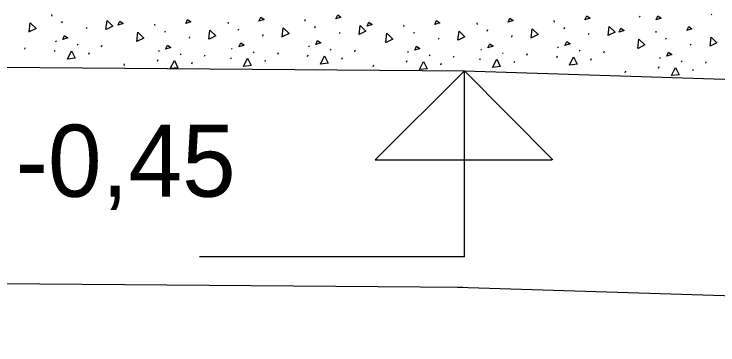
# Model space of a CAD drawing. Extents: x 43.6 to 54.1, y -16.5 to -1.7.
# Drawn here: x 48.509 to 49.485, y -8.702 to -8.243 of the extents above; entities that cross this region are included whole.
import ezdxf

# ---------------------------------------------------------------- set-up
doc = ezdxf.new("R2010")
doc.units = 0
for name, color, linetype in [('KONSTRUKCE_L', 7, 'Continuous'), ('Nová vrstva (1)', 7, 'Continuous'), ('Vrstva 50', 7, 'Continuous')]:
    doc.layers.add(name, color=color, linetype=linetype)

msp = doc.modelspace()

# ---------------------------------------------------------------- linework, layer by layer
at = {"layer": 'KONSTRUKCE_L'}
for p, q in [((46.54927, -8.30077), (49.13382, -8.32145)), ((49.13382, -8.32145), (51.63382, -8.40145))]:
    msp.add_line(p, q, dxfattribs=at)
at = {"layer": 'Nová vrstva (1)'}
for p, q in [((46.54927, -8.60078), (49.13142, -8.62144)), ((49.12422, -8.6213), (51.63382, -8.7016))]:
    msp.add_line(p, q, dxfattribs=at)
at = {"layer": 'Vrstva 50'}
for p, q in [((48.56142, -8.24343), (48.56178, -8.24542)), ((49.37598, -8.24574), (49.37692, -8.24711)), ((49.47593, -8.24264), (49.47687, -8.24391)), ((48.57567, -8.25471), (48.57651, -8.25268)), ((48.80571, -8.25364), (48.80607, -8.25563)), ((48.91232, -8.25034), (48.91268, -8.25233)), ((49.15108, -8.25502), (49.15144, -8.25701)), ((49.25769, -8.25172), (49.25805, -8.25371)), ((48.60972, -8.26279), (48.61046, -8.26077)), ((48.70412, -8.25669), (48.70448, -8.25868)), ((48.71836, -8.26796), (48.7192, -8.26594)), ((48.81996, -8.26492), (48.8208, -8.26289)), ((48.92656, -8.26162), (48.9274, -8.25959)), ((49.04949, -8.25807), (49.04985, -8.26006)), ((49.16533, -8.2663), (49.16617, -8.26427)), ((49.27194, -8.263), (49.27278, -8.26097)), ((48.75242, -8.27615), (48.75316, -8.27412)), ((48.85402, -8.2731), (48.85476, -8.27108)), ((48.96062, -8.2697), (48.96136, -8.26768)), ((49.06373, -8.26935), (49.06457, -8.26732)), ((49.0978, -8.27753), (49.09854, -8.2755)), ((49.19939, -8.27448), (49.20013, -8.27246)), ((49.30599, -8.27108), (49.30673, -8.26906)), ((49.39901, -8.26636), (49.39937, -8.26835)), ((49.41325, -8.27763), (49.41409, -8.27561)), ((48.56672, -8.27989), (48.56766, -8.28126)), ((48.59677, -8.28459), (48.59771, -8.28596)), ((49.44731, -8.28582), (49.44805, -8.28379)), ((48.52408, -8.29127), (48.52492, -8.28925)), ((48.56546, -8.29453), (48.5664, -8.29251)), ((48.63069, -8.28798), (48.63153, -8.28595)), ((48.70942, -8.29324), (48.71035, -8.29442)), ((48.81101, -8.2902), (48.81195, -8.29137)), ((48.84106, -8.2949), (48.842, -8.29617)), ((48.91761, -8.2868), (48.91856, -8.28817)), ((48.94767, -8.2915), (48.94861, -8.29287)), ((48.98159, -8.29488), (48.98243, -8.29286)), ((49.05479, -8.29463), (49.05572, -8.2958)), ((49.15638, -8.29158), (49.15732, -8.29275)), ((49.26299, -8.28818), (49.26393, -8.28955)), ((49.29304, -8.29288), (49.29398, -8.29425)), ((49.32696, -8.29626), (49.3278, -8.29424)), ((48.61298, -8.29811), (48.61382, -8.29609)), ((48.73947, -8.29794), (48.74041, -8.29922)), ((48.77339, -8.30123), (48.77422, -8.2992)), ((48.80975, -8.30484), (48.81069, -8.30281)), ((48.87498, -8.29818), (48.87582, -8.29616)), ((48.91635, -8.30144), (48.91729, -8.29941)), ((48.96388, -8.30502), (48.96472, -8.30299)), ((49.08484, -8.29933), (49.08578, -8.3006)), ((49.11876, -8.30261), (49.1196, -8.30058)), ((49.15512, -8.30622), (49.15606, -8.30419)), ((49.18644, -8.29628), (49.18737, -8.29755)), ((49.22035, -8.29956), (49.22119, -8.29754)), ((49.26173, -8.30282), (49.26266, -8.30079)), ((49.30925, -8.3064), (49.31009, -8.30437)), ((49.4043, -8.30291), (49.40524, -8.30409)), ((48.66179, -8.31382), (48.66263, -8.3118)), ((48.70816, -8.30789), (48.7091, -8.30586)), ((48.75568, -8.31146), (48.75652, -8.30944)), ((48.85728, -8.30842), (48.85812, -8.30639)), ((49.00716, -8.3152), (49.008, -8.31318)), ((49.05353, -8.30927), (49.05447, -8.30724)), ((49.10106, -8.31285), (49.1019, -8.31082)), ((49.20265, -8.3098), (49.20349, -8.30777)), ((49.43436, -8.30762), (49.4353, -8.30889)), ((49.46827, -8.3109), (49.46911, -8.30887)), ((49.13382, -8.32145), (49.01022, -8.44505)), ((49.13382, -8.32145), (49.25622, -8.44505)), ((49.13382, -8.57945), (49.13382, -8.32265)), ((49.35667, -8.32349), (49.35751, -8.32147)), ((49.40304, -8.31756), (49.40398, -8.31553)), ((49.45057, -8.32114), (49.45141, -8.31911)), ((49.01022, -8.44505), (49.25502, -8.44505)), ((49.13382, -8.57945), (48.76662, -8.57945))]:
    msp.add_line(p, q, dxfattribs=at)
for points in [[(48.95551, -8.24924), (48.95804, -8.24367), (48.96254, -8.24683), (48.95551, -8.24924)], [(49.30088, -8.25063), (49.30341, -8.24505), (49.30791, -8.24821), (49.30088, -8.25063)], [(49.39944, -8.25084), (49.40187, -8.24516), (49.40647, -8.24842), (49.39944, -8.25084)], [(48.53017, -8.26758), (48.53159, -8.25483), (48.53973, -8.26279), (48.53037, -8.26747)], [(48.63678, -8.26418), (48.6382, -8.25153), (48.64634, -8.25949), (48.63698, -8.26418)], [(48.65341, -8.25805), (48.65594, -8.25237), (48.66044, -8.25564), (48.65341, -8.25805)], [(48.74731, -8.25569), (48.74984, -8.25001), (48.75434, -8.25328), (48.74731, -8.25569)], [(48.8489, -8.25264), (48.85143, -8.24696), (48.85593, -8.25023), (48.8489, -8.25264)], [(48.99878, -8.25943), (49.00131, -8.25375), (49.00581, -8.25702), (48.99878, -8.25943)], [(49.09268, -8.25707), (49.09521, -8.25139), (49.09971, -8.25466), (49.09268, -8.25707)], [(49.19427, -8.25402), (49.1968, -8.24835), (49.2013, -8.25161), (49.19427, -8.25402)], [(48.77948, -8.27754), (48.7809, -8.26479), (48.78904, -8.27275), (48.77967, -8.27743)], [(48.88107, -8.27449), (48.88249, -8.26174), (48.89063, -8.2697), (48.88127, -8.27438)], [(48.98768, -8.27109), (48.9891, -8.25844), (48.99724, -8.2664), (48.98788, -8.27108)], [(49.12485, -8.27892), (49.12627, -8.26617), (49.13441, -8.27413), (49.12505, -8.27881)], [(49.22644, -8.27587), (49.22786, -8.26312), (49.236, -8.27108), (49.22664, -8.27576)], [(49.33305, -8.27247), (49.33447, -8.25982), (49.34261, -8.26778), (49.33325, -8.27247)], [(49.3483, -8.26772), (49.35083, -8.26204), (49.35533, -8.26531), (49.3483, -8.26772)], [(49.4422, -8.26536), (49.44473, -8.25968), (49.44923, -8.26295), (49.4422, -8.26536)], [(48.57676, -8.27799), (48.5793, -8.27241), (48.5839, -8.27557), (48.57676, -8.27799)], [(48.67953, -8.28063), (48.68094, -8.26789), (48.68909, -8.27585), (48.67972, -8.28053)], [(49.0249, -8.28202), (49.02632, -8.26927), (49.03446, -8.27723), (49.02509, -8.28191)], [(49.47437, -8.28721), (49.47578, -8.27446), (49.48393, -8.28242), (49.47456, -8.2871)], [(48.71946, -8.29134), (48.722, -8.28566), (48.7266, -8.28893), (48.71946, -8.29134)], [(48.82106, -8.28829), (48.82359, -8.28262), (48.82819, -8.28588), (48.82106, -8.28829)], [(48.92766, -8.2849), (48.9302, -8.27932), (48.93479, -8.28248), (48.92766, -8.2849)], [(49.16643, -8.28968), (49.16896, -8.284), (49.17356, -8.28726), (49.16643, -8.28968)], [(49.27303, -8.28628), (49.27557, -8.2807), (49.28016, -8.28386), (49.27303, -8.28628)], [(49.37441, -8.2903), (49.37583, -8.27756), (49.38397, -8.28552), (49.37461, -8.2902)], [(48.58318, -8.30511), (48.58884, -8.29363), (48.59385, -8.30389), (48.58348, -8.3051)], [(49.06484, -8.29272), (49.06737, -8.28704), (49.07197, -8.29031), (49.06484, -8.29272)], [(49.41435, -8.30101), (49.41688, -8.29533), (49.42148, -8.2986), (49.41435, -8.30101)], [(48.82747, -8.31531), (48.83313, -8.30394), (48.83814, -8.31419), (48.82777, -8.3153)], [(48.93408, -8.31202), (48.93974, -8.30054), (48.94475, -8.3108), (48.93438, -8.31201)], [(49.27945, -8.3134), (49.28511, -8.30192), (49.29012, -8.31218), (49.27975, -8.31339)], [(48.72588, -8.31836), (48.73154, -8.30699), (48.73655, -8.31724), (48.72618, -8.31835)], [(49.07125, -8.31974), (49.07691, -8.30837), (49.08192, -8.31862), (49.07155, -8.31973)], [(49.17284, -8.3167), (49.1785, -8.30532), (49.18351, -8.31557), (49.17314, -8.31669)], [(49.42077, -8.32803), (49.42643, -8.31666), (49.43144, -8.32691), (49.42107, -8.32802)]]:
    msp.add_lwpolyline(points, dxfattribs=at)

# ---------------------------------------------------------------- texts
msp.add_text('-0,45', height=0.1, dxfattribs=at).set_placement((48.51181, -8.49605))

doc.saveas('drawing.dxf')
